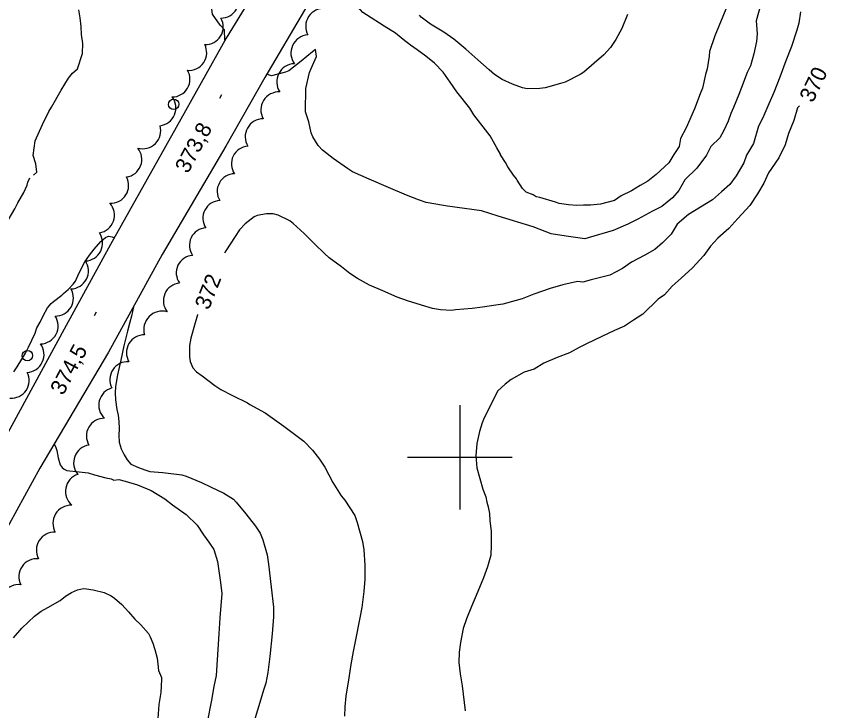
# Model space of a CAD drawing. Extents: x 287698 to 290158, y 5234163 to 5237182.
# Drawn here: x 288115.1 to 288270.6, y 5235351.5 to 5235484.4 of the extents above; entities that cross this region are included whole.
import ezdxf

# ---------------------------------------------------------------- set-up
doc = ezdxf.new("R2010")
doc.units = 0
for name, color, linetype in [('Niveau 1', 7, 'Continuous'), ('Niveau 2', 7, 'Continuous'), ('Niveau 21', 7, 'Continuous'), ('Niveau 3', 7, 'Continuous'), ('Niveau 36', 7, 'Continuous'), ('Niveau 44', 7, 'Continuous'), ('Niveau 61', 7, 'Continuous')]:
    doc.layers.add(name, color=color, linetype=linetype)

msp = doc.modelspace()

# ---------------------------------------------------------------- linework, layer by layer
at = {"layer": 'Niveau 1'}
msp.add_lwpolyline([(288264.98, 5235467.25), (288264.62, 5235466.83), (288263.9, 5235464.43), (288262.84, 5235461.96), (288262.21, 5235459.77), (288261.02, 5235457.28), (288259.04, 5235454.39), (288258.12, 5235452.46), (288256.93, 5235450.39), (288255.47, 5235448.18), (288253.2, 5235445.69), (288251.46, 5235443.75), (288249.32, 5235441.93), (288247.97, 5235440.41), (288246.65, 5235438.61), (288244.51, 5235436.25), (288242.36, 5235434.3), (288240.62, 5235432.77), (288239.15, 5235431.11), (288237.94, 5235430.26), (288234.99, 5235427.35), (288233.24, 5235426.22), (288231.48, 5235425.1), (288229.59, 5235424.24), (288227.16, 5235423.1), (288224.19, 5235421.69), (288222.83, 5235420.98), (288220.94, 5235419.98), (288218.64, 5235419.12), (288216.07, 5235417.98), (288214.18, 5235416.85), (288212.28, 5235416.28), (288209.84, 5235414.87), (288208.64, 5235414.02), (288207.17, 5235412.64), (288206.11, 5235410.43), (288204.66, 5235407.54), (288204.27, 5235406.58), (288203.76, 5235404.93), (288203.26, 5235402.61), (288203.03, 5235400.28), (288203.22, 5235397.97), (288203.8, 5235395.94), (288204.39, 5235393.91), (288204.96, 5235392.42), (288205.13, 5235391.43), (288205.43, 5235390.55), (288205.66, 5235389.26), (288205.75, 5235387.89), (288205.99, 5235385.79), (288205.98, 5235383.27), (288205.89, 5235381.25), (288205.3, 5235379.04), (288204.52, 5235376.94), (288203.41, 5235374.29), (288202.23, 5235371.46), (288201.25, 5235369.11), (288200.64, 5235367.22), (288200.09, 5235364.56), (288199.89, 5235362.74), (288199.82, 5235360.72), (288200.04, 5235358.57), (288200.43, 5235356.3), (288201.03, 5235351.48)], dxfattribs=at)
at = {"layer": 'Niveau 2'}
for points in [[(288201.87, 5235466.8), (288199.4, 5235469.89), (288198.12, 5235471.74), (288196.83, 5235473.66), (288195.16, 5235475.43), (288193.49, 5235476.72), (288191.83, 5235477.94), (288190.56, 5235478.85), (288189.14, 5235479.92), (288187.7, 5235481.13), (288185.5, 5235482.5), (288182.11, 5235484.63), (288181.46, 5235485.09), (288180.11, 5235486.63), (288179.3, 5235487.74), (288177.78, 5235490.11), (288177.15, 5235491.28), (288177.38, 5235493.05), (288178.28, 5235495.24), (288179.04, 5235497.05)], [(288154.97, 5235481.81), (288154.12, 5235482.67), (288152.65, 5235484.77), (288152.39, 5235486.77), (288153.88, 5235490.31), (288153.96, 5235490.75)], [(288257.73, 5235487.15), (288256.66, 5235483.48), (288256.85, 5235481.03), (288256.73, 5235479.53), (288256.23, 5235477.2), (288255.59, 5235474.87), (288254.94, 5235473.63), (288253.9, 5235470.75), (288253.38, 5235469.38), (288252.34, 5235466.9), (288251.82, 5235465.8), (288251.3, 5235464.29), (288250.51, 5235462.5), (288249.72, 5235461.13), (288247.98, 5235459.45), (288247.19, 5235457.81), (288245.33, 5235455.32), (288243.05, 5235453.1), (288241.86, 5235451.02), (288240.65, 5235449.64), (288238.65, 5235447.96), (288236.88, 5235447.11), (288234.05, 5235445.56), (288232.16, 5235444.57), (288229.31, 5235443.42), (288224.57, 5235441.97), (288223.89, 5235441.82), (288220.33, 5235442.3), (288217.45, 5235442.78), (288214.01, 5235444.09), (288207.29, 5235446.14), (288204.13, 5235447.17), (288197.61, 5235448.06), (288196.86, 5235448.19), (288193.56, 5235448.76), (288192.08, 5235449.23), (288189.78, 5235450.13), (288186.35, 5235451.6), (288182.61, 5235453.22), (288179.45, 5235454.6), (288178.5, 5235455.22), (288175.75, 5235457.17), (288173.71, 5235458.78), (288172.88, 5235459.68), (288171.85, 5235461.29), (288171.54, 5235462.1), (288171.07, 5235464.17), (288170.48, 5235466.07), (288170.45, 5235466.21)], [(288251.6, 5235487.5), (288250.28, 5235484.36), (288248.76, 5235480.63), (288247.74, 5235477.61), (288247.68, 5235476.77), (288247.31, 5235474.35), (288247.01, 5235473.26), (288246.41, 5235470.65), (288245.98, 5235469.55), (288244.86, 5235466.64), (288243.27, 5235463.04), (288242.22, 5235460.98), (288241.98, 5235459.48), (288240.9, 5235457.96), (288239.99, 5235456.31), (288237.57, 5235454.08), (288235.96, 5235452.82), (288234.47, 5235451.97), (288232.86, 5235450.99), (288230.83, 5235449.99), (288229.61, 5235449.16), (288226.89, 5235448.42), (288224.99, 5235448.25), (288223.63, 5235448.22), (288222.4, 5235448.2), (288220.76, 5235448.3), (288218.98, 5235448.54), (288218.29, 5235448.8), (288215.28, 5235449.69), (288214.58, 5235449.82), (288214.04, 5235450.22), (288212.66, 5235450.73), (288211.96, 5235451.4), (288210.98, 5235453.02), (288210.84, 5235453.29), (288210.27, 5235453.96), (288209.15, 5235455.58), (288208.73, 5235456.39), (288207.75, 5235457.87), (288207.74, 5235458), (288207.04, 5235459.22), (288206.75, 5235459.75), (288205.77, 5235461.51), (288202.64, 5235465.51), (288201.87, 5235466.8)], [(288118.45, 5235454), (288119.03, 5235454.52), (288118.84, 5235456.13), (288118.37, 5235457.74), (288118.75, 5235460.54), (288120.14, 5235463.65), (288121.33, 5235466.13), (288121.86, 5235467), (288123.71, 5235470.24), (288125.12, 5235472.51), (288125.9, 5235473.48), (288126.87, 5235474.3), (288127.78, 5235477.23), (288127.83, 5235479.17), (288127.63, 5235480.89), (288127.53, 5235482.44), (288127.34, 5235484.08), (288127.08, 5235485.63)], [(288265.16, 5235485.21), (288264.83, 5235483.08), (288264.48, 5235481.74), (288263.44, 5235478.57), (288262.38, 5235475.82), (288261.22, 5235472.75), (288260.06, 5235469.76), (288259.12, 5235467.6), (288257.95, 5235464.93), (288257.12, 5235463.37), (288256.16, 5235460.02), (288254.83, 5235457.82), (288254.32, 5235456.31), (288252.86, 5235453.83), (288251.67, 5235452.16), (288250.06, 5235450.77), (288248.31, 5235449.24), (288246.02, 5235447.83), (288243.73, 5235446.43), (288241.57, 5235444.62), (288240.39, 5235442.68), (288238.78, 5235441.01), (288237.3, 5235439.76), (288235.41, 5235438.64), (288232.84, 5235437.36), (288231.09, 5235436.09), (288228.66, 5235434.83), (288225.13, 5235433.94), (288223.5, 5235433.5), (288222.49, 5235433.66), (288219.69, 5235432.98), (288217.28, 5235432.29), (288214.15, 5235431.2), (288211.92, 5235430.3), (288210.78, 5235429.97), (288208.22, 5235429.27), (288206.88, 5235429.12), (288204.34, 5235428.69), (288202.32, 5235428.47), (288199.15, 5235428.22), (288198.37, 5235428.07), (288196.32, 5235428.18), (288194.75, 5235428.49), (288192.65, 5235429.12), (288189.97, 5235429.93), (288188.03, 5235430.62), (288185.23, 5235431.82), (288182.72, 5235432.96), (288180.38, 5235434.22), (288178.94, 5235435.14), (288177.37, 5235436.45), (288175.02, 5235438.18), (288174.1, 5235438.97), (288172.25, 5235440.77), (288170.22, 5235442.82), (288168.11, 5235444.76), (288167.46, 5235445.22), (288165.24, 5235446.31), (288164.27, 5235446.59), (288163.03, 5235446.55), (288161.19, 5235446.23), (288160.66, 5235445.99), (288158.89, 5235444.65), (288157.83, 5235443.54), (288156.98, 5235442.27), (288155.19, 5235439.51), (288154.94, 5235439.04)], [(288232.08, 5235484.69), (288230.96, 5235482.02), (288229.86, 5235479.9), (288228.79, 5235478.39), (288227.56, 5235476.99), (288225.69, 5235475.4), (288223.7, 5235473.71), (288222.98, 5235473.24), (288220.16, 5235471.8), (288219.27, 5235471.53), (288216.34, 5235470.69), (288215.32, 5235470.54), (288212.9, 5235470.48), (288211.98, 5235470.69), (288210.05, 5235471.4), (288208.09, 5235472.28), (288206.62, 5235473.24), (288205.59, 5235474.13), (288203.44, 5235476.03), (288201.12, 5235478.06), (288198.82, 5235480), (288196.94, 5235481.32), (288194.4, 5235482.88), (288192.58, 5235484.18), (288192.24, 5235484.57)], [(288155.05, 5235479.8), (288154.97, 5235481.81)], [(288171.8, 5235477.6), (288169.63, 5235475.77), (288167.24, 5235473.92), (288166.66, 5235473.65), (288163.93, 5235473), (288163.39, 5235473.19), (288163.14, 5235473.44)], [(288170.45, 5235466.21), (288170.5, 5235470.56), (288171.2, 5235473.59), (288171.53, 5235474.36), (288172.54, 5235476.7), (288172.35, 5235478.03), (288171.8, 5235477.6)], [(288097.31, 5235414.31), (288098.52, 5235416.52), (288099.82, 5235418.74), (288101.18, 5235421.13), (288102.09, 5235422.85), (288103.17, 5235425.09), (288104.21, 5235427.46), (288105.26, 5235429.61), (288106.74, 5235432.74), (288107.9, 5235434.99), (288109.67, 5235438.39), (288110.9, 5235440.56), (288112.03, 5235442.66), (288113.13, 5235444.59), (288114.87, 5235447.56), (288115.43, 5235448.67), (288116.55, 5235450.68), (288117.23, 5235452.06), (288117.36, 5235452.64), (288117.72, 5235453.47)], [(288124.16, 5235431.33), (288125.04, 5235432.08), (288126.04, 5235433.09), (288126.43, 5235433.71), (288127.11, 5235435.16), (288128.26, 5235437.4), (288129.14, 5235438.69), (288130.04, 5235439.83), (288131.33, 5235441.3), (288132.21, 5235442.05), (288132.77, 5235442.29), (288133.49, 5235442.19), (288133.85, 5235441.99)], [(288114.67, 5235416.33), (288115.28, 5235417.32), (288116.86, 5235419.9), (288117.45, 5235421.06), (288118.72, 5235423.75), (288119.09, 5235424.76), (288119.7, 5235425.82), (288120.26, 5235427.07), (288121.13, 5235428.58), (288121.82, 5235429.43), (288122.26, 5235429.8), (288123.82, 5235431.03), (288124.16, 5235431.33)], [(288137.55, 5235428.8), (288137.17, 5235427), (288136.82, 5235425.86), (288136.41, 5235424.13), (288135.78, 5235421.56), (288135.73, 5235421.32)], [(288149.8, 5235427.29), (288149.79, 5235427.28), (288149.35, 5235425.72), (288148.54, 5235422.82), (288148.29, 5235421.41), (288148.24, 5235419.2), (288148.37, 5235418.33), (288148.93, 5235417.13)], [(288135.73, 5235421.32), (288135.16, 5235418.55), (288134.78, 5235417.16), (288134.5, 5235415.77), (288134.11, 5235413.57), (288134.03, 5235412.31), (288134.11, 5235411.02), (288134.37, 5235409.16), (288134.62, 5235408.07), (288134.75, 5235406.86), (288134.79, 5235405.48), (288134.76, 5235404.14), (288134.84, 5235402.87), (288135.2, 5235401.63), (288135.74, 5235400.48), (288136.31, 5235399.54), (288137.04, 5235398.68), (288138.51, 5235398.07), (288138.51, 5235398.07)], [(288148.93, 5235417.13), (288149.58, 5235416.37), (288150.68, 5235415.59), (288153.11, 5235413.74), (288154.26, 5235412.98), (288156.5, 5235411.82), (288159.39, 5235410.4), (288159.84, 5235410.08), (288162.73, 5235408.5), (288163.65, 5235407.87), (288166.29, 5235405.95), (288170.11, 5235403.11), (288171.82, 5235401.33), (288173.17, 5235399.63), (288174.13, 5235398.14), (288175.72, 5235395.2), (288177.3, 5235392.65), (288177.96, 5235391.78), (288179.87, 5235388.89), (288180.37, 5235387.5), (288181.35, 5235383.89), (288181.6, 5235382.27), (288181.8, 5235379.39), (288181.82, 5235376.7), (288181.59, 5235374.34), (288181.23, 5235371.27), (288180.88, 5235369.26), (288179.94, 5235364.78), (288179.61, 5235362.86), (288179.11, 5235360.33), (288178.73, 5235357.79), (288178.2, 5235354.28), (288177.99, 5235352.23), (288177.95, 5235350.5)], [(288122.36, 5235402.49), (288122.63, 5235402.06), (288122.91, 5235401.27), (288123.12, 5235399.88), (288123.5, 5235398.57), (288123.88, 5235398.03), (288124.28, 5235397.7), (288124.78, 5235397.48), (288125.35, 5235397.38), (288126.56, 5235397.27), (288128.88, 5235397.01), (288130.12, 5235396.64), (288132.26, 5235396.06), (288133.31, 5235395.86), (288133.77, 5235395.65), (288134.77, 5235395.78)], [(288138.51, 5235398.07), (288139.7, 5235397.58), (288140.71, 5235397.31), (288143.18, 5235397.12), (288146.82, 5235396.63), (288147.66, 5235396.4), (288150.57, 5235395.18), (288152.44, 5235394.31), (288154.84, 5235393.11), (288156.66, 5235391.98), (288157.21, 5235391.44), (288159.02, 5235389.15), (288160.88, 5235386.83), (288161.76, 5235385.5), (288162.32, 5235384.18), (288163.12, 5235381.33), (288163.35, 5235379.57), (288163.9, 5235375.18), (288164.34, 5235371.3), (288164.37, 5235369.48), (288164.07, 5235366.19), (288163.63, 5235361.89), (288163.27, 5235358.82), (288162.87, 5235356.81), (288162.5, 5235355.63), (288161.3, 5235351.62), (288160.1, 5235347.86)], [(288134.77, 5235395.78), (288135.99, 5235395.4), (288138.34, 5235394.75), (288140.95, 5235393.63), (288143.57, 5235392.04), (288145, 5235390.88), (288147.61, 5235389.06), (288149.76, 5235387), (288150.97, 5235385.15), (288151.94, 5235383.76), (288152.9, 5235382.36), (288153.65, 5235380.04), (288154.2, 5235376.06), (288154.48, 5235373.95), (288154.1, 5235369.26), (288153.91, 5235366.21), (288153.34, 5235358.27), (288152.91, 5235356.15), (288152.49, 5235353.56), (288151.63, 5235349.32)], [(288114.57, 5235365.45), (288116.16, 5235367.29), (288117.38, 5235368.48), (288118.63, 5235369.6), (288119.88, 5235370.53), (288121.15, 5235371.24), (288123.5, 5235372.61), (288124.55, 5235373.4), (288125.68, 5235374.14), (288126.81, 5235374.63), (288127.98, 5235374.88), (288128.58, 5235374.84), (288129.86, 5235374.62), (288131.91, 5235374.1), (288133.28, 5235373.48), (288133.95, 5235373.03), (288135.31, 5235371.85), (288136.6, 5235370.46), (288137.78, 5235369.05), (288138.94, 5235367.94), (288140.41, 5235366.31), (288140.76, 5235365.67), (288141.24, 5235364.42), (288141.61, 5235363.23), (288142.05, 5235361.59), (288142.24, 5235360.44), (288142.34, 5235359.2), (288142.94, 5235357.85), (288142.94, 5235357.85)], [(288142.94, 5235357.85), (288142.92, 5235357.46), (288142.76, 5235354.98), (288142.39, 5235352.7), (288142.23, 5235350.02)]]:
    msp.add_lwpolyline(points, dxfattribs=at)
at = {"layer": 'Niveau 21'}
for points in [[(288412.58, 5235574.13), (288396.62, 5235568.2), (288378.32, 5235564.14), (288359.27, 5235561.33), (288339.36, 5235559.13), (288315.66, 5235557.22), (288295.2, 5235555.75), (288278, 5235554.48), (288263.36, 5235553.19), (288246.09, 5235550.65), (288233.2, 5235547.93), (288218.94, 5235544.37), (288206.85, 5235539.96), (288196.69, 5235533.87), (288187.01, 5235526.21), (288177.75, 5235515.57), (288171.84, 5235507.18), (288164.1, 5235494.63), (288155.28, 5235480.18), (288145.74, 5235463.07)], [(288404.36, 5235561.32), (288386.9, 5235556.35), (288372.55, 5235553.45), (288354.12, 5235551.14), (288335.81, 5235549.51), (288316.85, 5235548.63), (288300.02, 5235547.58), (288283.18, 5235546.56), (288266.22, 5235544.18), (288249.42, 5235540.87), (288230.59, 5235536.58), (288216.96, 5235532.39), (288205.61, 5235526.76), (288196.13, 5235519.89), (288186.88, 5235510.49), (288178.12, 5235498.91), (288170.26, 5235485.52), (288162.7, 5235472.69), (288155.23, 5235459.52)], [(288145.74, 5235463.07), (288133.14, 5235440.74), (288124.26, 5235424.52), (288112.67, 5235403.12), (288103.48, 5235387.01), (288090.93, 5235364.82), (288077.15, 5235342.5), (288067.25, 5235327.63), (288058.83, 5235315.4), (288048.75, 5235302.52), (288038.43, 5235291.29), (288025.6, 5235279.48), (288011.9, 5235268.02), (287998.22, 5235256.72), (287985.09, 5235246.31), (287972.54, 5235235), (287960.54, 5235223.89), (287948.27, 5235211.98)], [(288155.23, 5235459.52), (288143.04, 5235438.77), (288132.78, 5235420.12), (288119.66, 5235397.91), (288107.85, 5235376.49), (288093.91, 5235353.38), (288082.05, 5235333.18), (288072.8, 5235318.93), (288064.64, 5235307.5), (288054.21, 5235294.6), (288041.68, 5235281.78), (288027.97, 5235269.04), (288012.89, 5235256.33), (288000.22, 5235246.49), (287985.65, 5235235.27), (287973.66, 5235224.14), (287962.81, 5235213.28)]]:
    msp.add_lwpolyline(points, dxfattribs=at)
at = {"layer": 'Niveau 3'}
for p, q in [((288154.07, 5235468.68), (288154.45, 5235469.38)), ((288130.1, 5235427.15), (288130.5, 5235427.84))]:
    msp.add_line(p, q, dxfattribs=at)
at = {"layer": 'Niveau 36'}
for centre in [(288145.24, 5235467.52), (288117.26, 5235419.45)]:
    msp.add_ellipse(centre, major_axis=(0.918, 0.397), ratio=0.999992, dxfattribs=at)
at = {"layer": 'Niveau 44'}
for centre, radius, start, end in [((288144.99, 5235472.32), 3.37, 268.7859, 30.5891), ((288142.24, 5235466.83), 3.42, 276.5373, 38.4), ((288139.32, 5235462.47), 3.44, 254.1214, 16.1476), ((288135.75, 5235457), 3.4, 277.7167, 39.4327), ((288159.63, 5235456.16), 3.35, 93.2592, 215.0134), ((288133.23, 5235452), 3.4, 266.8693, 28.588), ((288143.04, 5235424.44), 3.52, 74.5715, 196.4822)]:
    msp.add_arc(centre, radius, start, end, dxfattribs=at)
for centre, major_axis, ratio, start_param, end_param in [((288154.3, 5235487.42), (2.88, -1.81), 0.998256, 5.267886, 7.388654), ((288173.97, 5235482.41), (-2.7, 2.19), 0.999605, 5.319133, 7.446389), ((288151.32, 5235482.36), (2.91, -1.77), 0.997497, 5.216977, 7.339979), ((288171.14, 5235477.33), (-2.97, 1.81), 0.999691, 5.333801, 7.460499), ((288148.17, 5235477.41), (2.82, -1.88), 0.999796, 5.218873, 7.348432), ((288168.43, 5235471.82), (-2.86, 1.97), 0.999767, 5.345785, 7.475197), ((288165.38, 5235466.44), (-2.87, 1.95), 0.997929, 5.258755, 7.388285), ((288162.36, 5235461.32), (-2.95, 1.78), 0.997679, 5.255925, 7.382833), ((288156.91, 5235450.89), (-2.26, 2.47), 0.999959, 5.545196, 7.676631), ((288130.46, 5235446.33), (3.21, -1.26), 0.997684, 5.258224, 7.383467), ((288154.17, 5235445.76), (0.18, -3.34), 0.999994, 3.114391, 5.244885), ((288151.59, 5235440.57), (-2.59, 2.11), 0.999924, 5.456734, 7.586172), ((288128.19, 5235441), (3.09, -1.54), 0.997793, 5.21867, 7.338188), ((288149.08, 5235435.29), (-3.02, 1.44), 0.999977, 5.221483, 7.345126), ((288125.48, 5235435.65), (2.87, -1.91), 0.999687, 5.329755, 7.458414), ((288122.62, 5235430.46), (2.89, -1.88), 0.998492, 5.272141, 7.392081), ((288146.7, 5235429.93), (-3.15, 1.36), 0.999911, 5.219772, 7.348998), ((288119.68, 5235425.13), (3.03, -1.66), 0.99582, 5.242914, 7.364862), ((288139.66, 5235420.01), (-3.02, 1.68), 0.990661, 5.212645, 7.320782), ((288116.97, 5235419.68), (3.09, -1.58), 0.996977, 5.25733, 7.375704), ((288136.47, 5235414.86), (-2.9, 1.85), 0.995944, 5.215746, 7.333478), ((288114.11, 5235414.75), (2.92, -1.93), 0.979446, 5.2313, 7.321795), ((288134.32, 5235409.97), (-3.18, 1.24), 0.99976, 5.345679, 7.475299), ((288132.02, 5235404.03), (-3.03, 1.74), 0.980118, 5.234588, 7.325349), ((288129.54, 5235398.94), (-3.23, 1.19), 0.998002, 5.216345, 7.337989), ((288127.97, 5235393.45), (-3.38, 0.65), 0.998401, 5.215379, 7.340303), ((288125.64, 5235387.34), (-3.02, 1.79), 0.991824, 5.215128, 7.328974), ((288122.41, 5235382.22), (-2.83, 1.96), 0.998098, 5.266855, 7.386187), ((288119.07, 5235377.16), (-2.84, 1.94), 0.999994, 5.218887, 7.346732), ((288115.58, 5235372.21), (-2.78, 2.03), 0.999994, 5.223273, 7.347655)]:
    msp.add_ellipse(centre, major_axis=major_axis, ratio=ratio, start_param=start_param, end_param=end_param, dxfattribs=at)
at = {"layer": 'Niveau 61'}
for points in [[(288200, 5235410), (288200, 5235400), (288200, 5235390)], [(288190, 5235400), (288200, 5235400), (288210, 5235400)]]:
    msp.add_lwpolyline(points, dxfattribs=at)

# ---------------------------------------------------------------- texts
at = {"layer": 'Niveau 1'}
msp.add_text('370', height=3, rotation=64.0174, dxfattribs=at).set_placement((288267.51, 5235467.69))
at = {"layer": 'Niveau 2'}
msp.add_text('372', height=3, rotation=68.2815, dxfattribs=at).set_placement((288151.95, 5235428.05))
at = {"layer": 'Niveau 3'}
for s, rotation, p in [('373,8', 61.7993, (288147.96, 5235454.13)), ('374,5', 61.6903, (288124.08, 5235411.7))]:
    msp.add_text(s, height=3, rotation=rotation, dxfattribs=at).set_placement(p)

doc.saveas('drawing.dxf')
